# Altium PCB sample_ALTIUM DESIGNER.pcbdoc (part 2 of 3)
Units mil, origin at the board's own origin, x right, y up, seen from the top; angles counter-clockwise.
Board outline 2485.01 x 1905 mil, 6 copper layers (1 TallParts (2oz), 2 RTNS (2oz), 3 InternalPlane1 (2 oz), 4 InternalPlane2 (2 oz), 5 Signal (2oz), 6 LoParts (2oz)), stack 46.8 mil thick; 176 components, 89 nets, 769 pads, 0 vias.
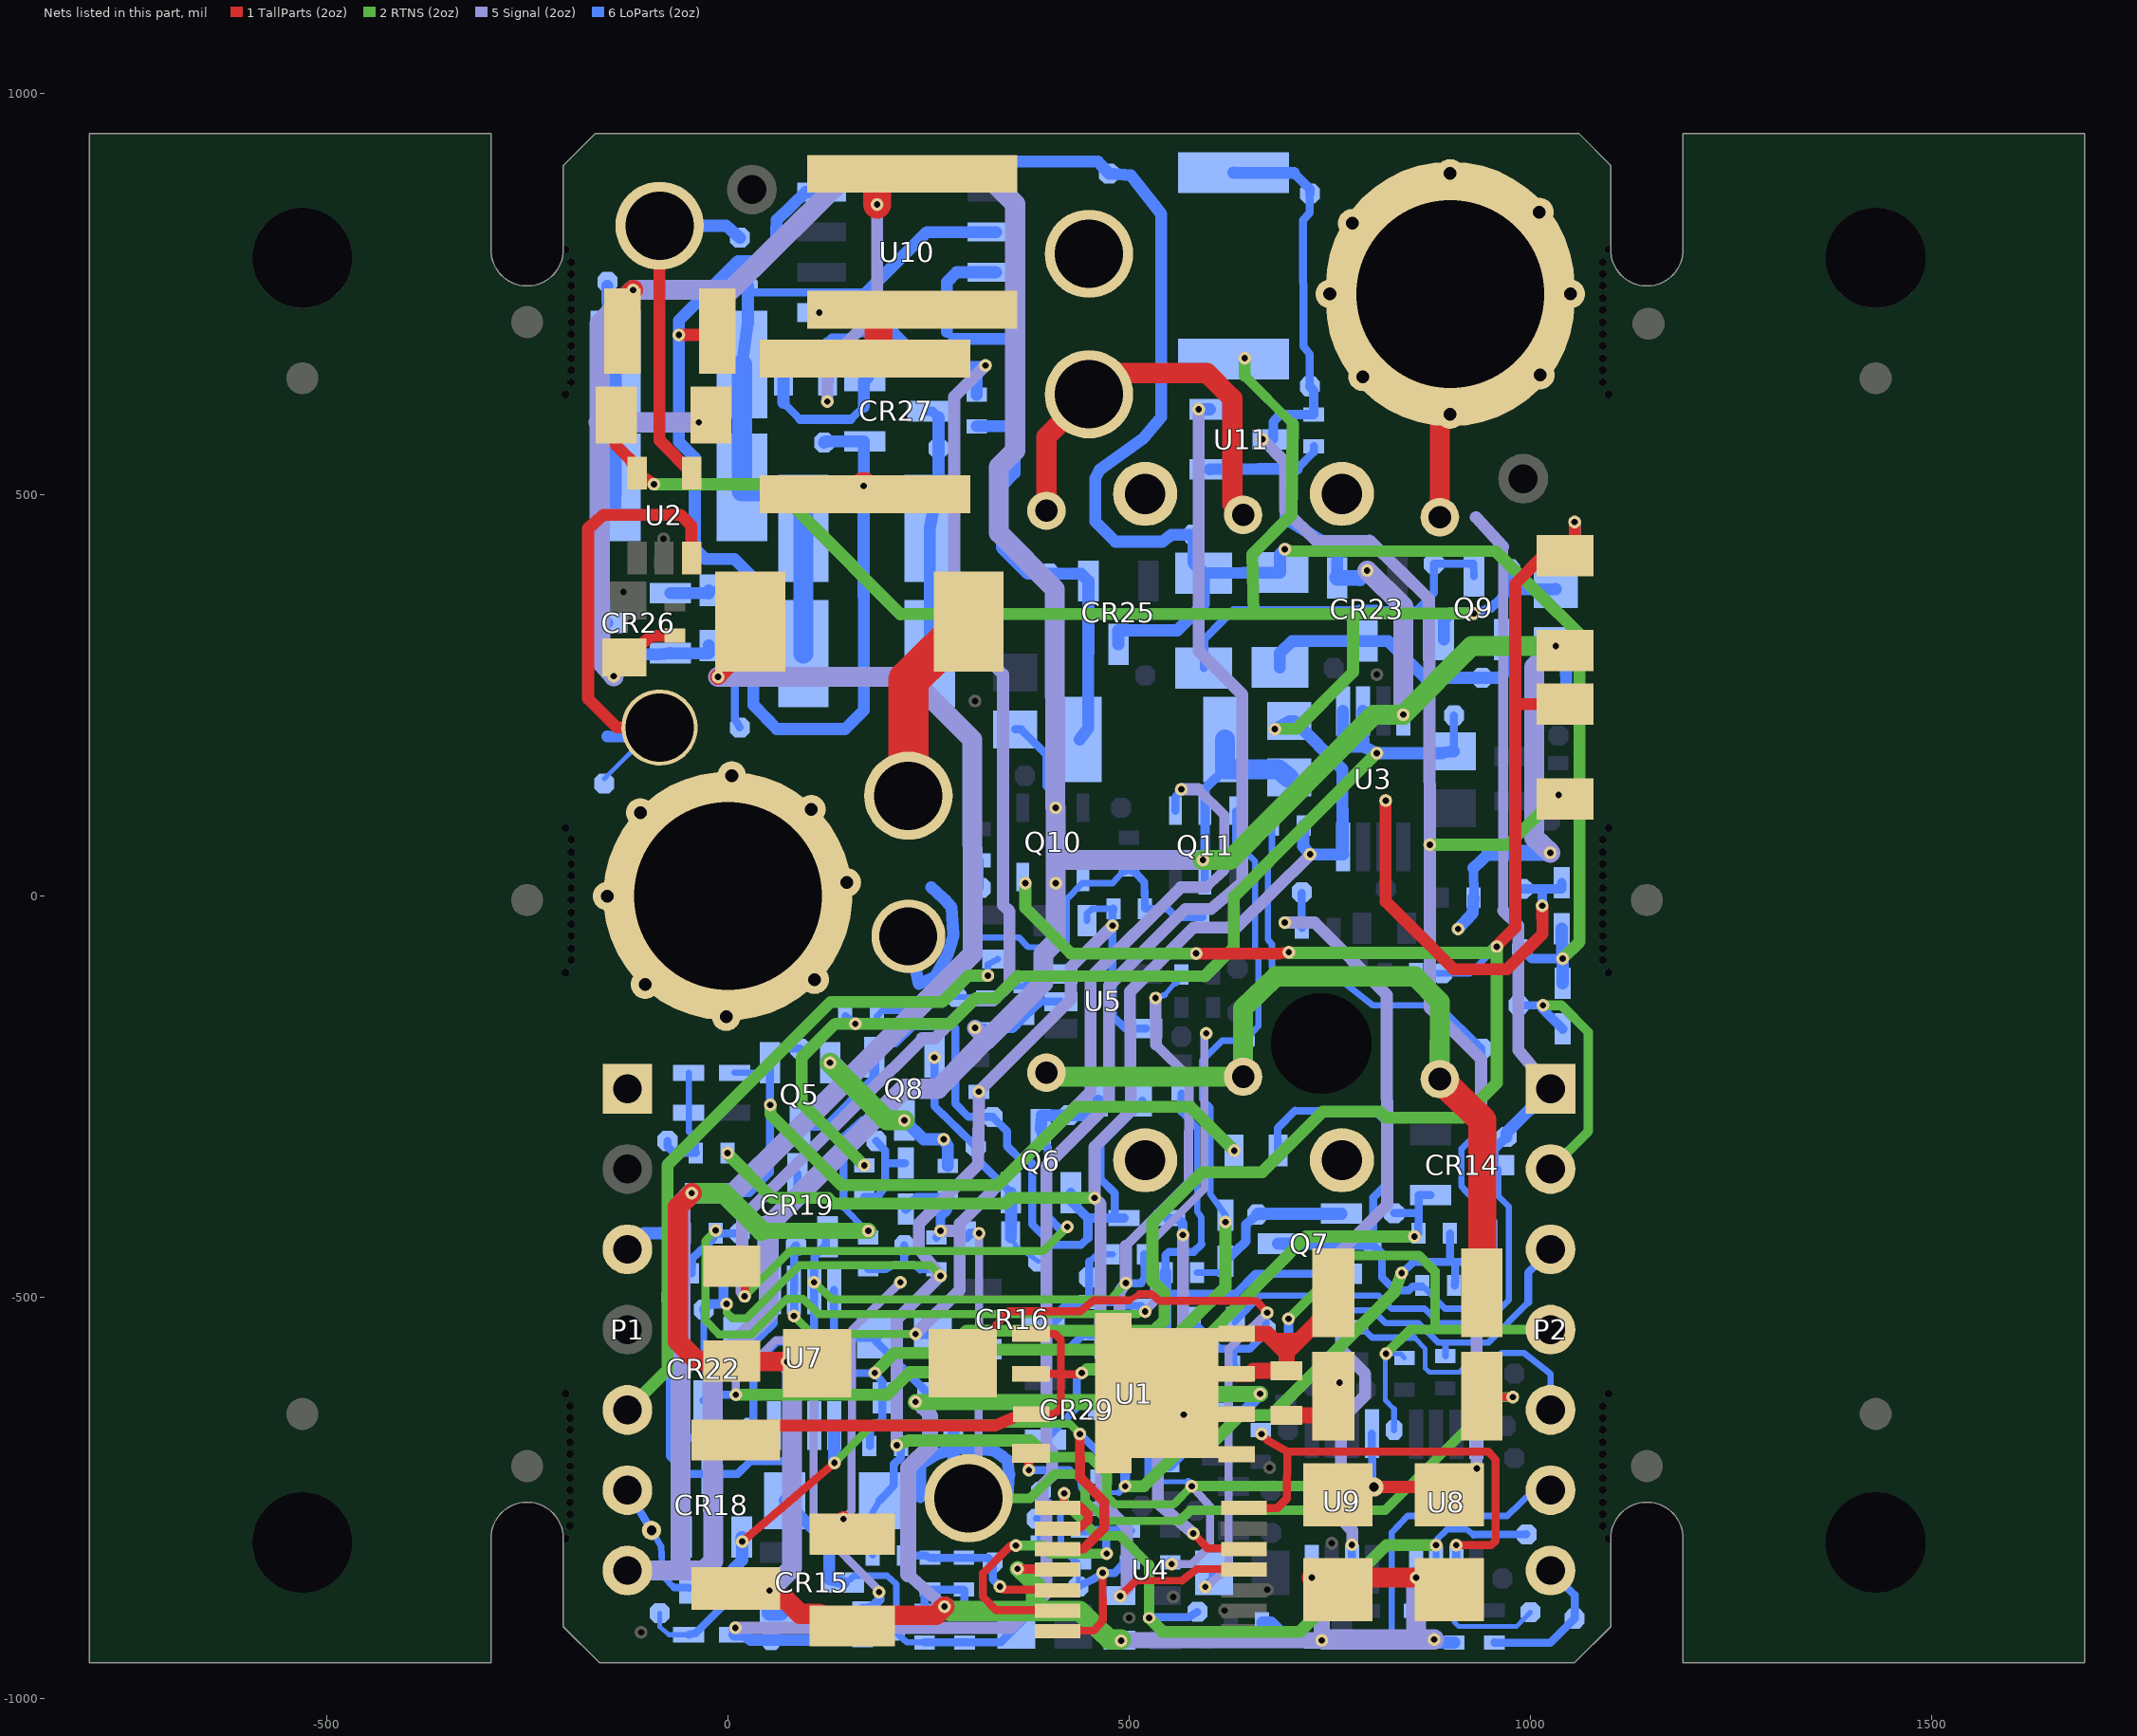
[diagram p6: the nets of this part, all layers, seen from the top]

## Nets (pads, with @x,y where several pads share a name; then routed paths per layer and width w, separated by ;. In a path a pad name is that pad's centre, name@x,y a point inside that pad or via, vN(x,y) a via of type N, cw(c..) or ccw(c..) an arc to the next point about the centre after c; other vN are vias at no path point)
5V_REG: C8.2 C13.1 C20.1 C21.1 C28.1 C33.2 pad.1@805,-736 pad.2@210.5,-684 pad.2@265.01,-473 pad.2@312.73,-243.69 pad.2@479.25,-36.85 pad.2@553,-832 pad.2@578,-735 pad.2@666,569 pad.2@874.6,64 pad.2@933,-713 pad.2@1035.01,126 pad.2@-1.5,-508 pad.8@220.01,-435 pad.8@725,635 pad.8@725,875 pad.8@-29.99,-515 R5.2 R9.2 R12.1 R14.2 R35.2 R36.2 R66.2 R67.2 R71.1 R86.2 R92.2 U5.5 U7.8 U8.8 U9.8 U11.3 | length 5291.2
  1 TallParts (2oz) w12: C20.1@760.01,-745.94 769.96,-736 pad.1@805,-736
  1 TallParts (2oz) w15: pad.1@805,-736 888,-736 C21.1@899,-745.94 917.5,-745.5 933,-730.5 pad.2@933,-713
  2 RTNS (2oz) w10: pad.2@-1.5,-508 -1.5,-519 6,-526 23.5,-526 89,-460 253,-460 pad.2@265.01,-473 ; 472.5,-747.5 482.5,-757.5 555.5,-757.5 pad.2@578,-735
  2 RTNS (2oz) w12: 451,-699 472.54,-719.54 472.5,-747.5
  2 RTNS (2oz) w13: 399,-699 451,-699 ; pad.2@578,-735 795,-735 pad.1@805,-736
  2 RTNS (2oz) w15: pad.2@210.5,-684 225,-678 377,-678 399,-699 ; pad.2@874.6,64 972.3,64 pad.2@1034.61,126.31
  5 Signal (2oz) w10: pad.2@554,-832 578,-832 601,-809 601,-760 pad.2@578,-735
  5 Signal (2oz) w15: pad.2@210.5,-684 210.5,-527.5 pad.2@265.01,-473 238,-439 238,-408 312,-334 pad.2@312.73,-243.69 ; pad.2@313,-243.42 313.5,-242.5 427.5,-128.5 427,-89.11 pad.2@479.25,-36.85 ; pad.2@666,569 694,541 694.5,480.5 733,442.5 799.5,443 873.5,370 874.75,64 874.69,63.92 pad.2@874.6,63.81 ; pad.2@874.6,64 pad.2@874.6,63.81 ; pad.2@933,-713 933,-266 938.5,-261 938.5,-203.11 874.6,-139.2 pad.2@874.6,63.81
  6 LoParts (2oz) w6: 528.5,-729.5 pad.2@573.5,-729.5
  6 LoParts (2oz) w8: pad.8@-29.99,-515 -30,-573 -55,-598 -55,-666 -45.5,-676 -5,-676 5.5,-687 45.5,-687 57.5,-676 U7.8@57.5,-659.65 ; R12.1@180.32,-821.27 180.32,-767.74 R9.2@189.06,-753 ; R5.2@447.57,-30.54 447.57,-21.93 453.77,-15.73 R86.2@480.31,-15.73 ; 524,-726 528.5,-729.5
  6 LoParts (2oz) w10: C13.1@175.01,-464.69 197,-464.5 206,-460 220,-460 ; R9.2@189.06,-753 207,-734 207,-707.5 215.5,-699.5 R67.2@215.41,-685 ; pad.8@220.01,-435 220,-460 ; pad.2@265.01,-473 R66.2@260,-464.69 240,-465 233,-460 220,-460 ; R86.2@480.31,-15.73 479,-22.5 pad.2@479.25,-36.85 479.5,-149.5 495.5,-165 U5.5@521,-165 ; 524,-726 524,-692 526.31,-689.69 C33.2@526.31,-678 ; pad.2@573.5,-729.5 pad.2@578,-735 ; pad.2@666,569 U11.3@679.37,569 ; pad.8@725,635 725,675 717,685 716.5,842 725,851 pad.8@725,875 ; U9.8@802.5,-669.35 803,-728 pad.1@805,-736 ; U8.8@932.51,-670.35 933,-676.5 pad.2@933,-713
  6 LoParts (2oz) w12: pad.8@-29.99,-515 -22.99,-508 pad.2@-1.5,-508 -5.3,-504.2 R14.2@-5.3,-470 ; pad.2@210.5,-684 214.69,-684 R67.2@215.69,-685 ; R36.2@551,-829.69 553,-831.69 pad.2@553,-832 ; U11.3@679.37,569 679.5,590.5 687.5,599.5 C28.1@730,599.69 730,629 pad.8@725,635 ; 705.5,900.5 725,881 pad.8@725,875
  6 LoParts (2oz) w15: R71.1@630,901.14 705.5,900.5
28V_BIAS_IN: CR7.1 P2.2 pad.2@1015.6,-136 pad.8@985,-136 | length 330.7
  2 RTNS (2oz) w10: pad.2@1015.81,-136.2 pad.2@1016,-136
  2 RTNS (2oz) w12: pad.2@1015.6,-136 1016,-136 1038.5,-136 1072,-169.5 1072,-293 P2.2@1025,-340
  6 LoParts (2oz) w10: pad.8@985,-136 pad.2@1015.6,-136
  6 LoParts (2oz) w12: pad.2@1015.6,-136 1015.6,-141.1 CR7.1@1040,-165.5
28VA: CR8.1 CR13.1 E1.1 E2.1 FL1.2 FL2.2 pad.2@819.6,119 pad.2@1014.61,-12 pad.8@989.61,9 | length 1071.2
  1 TallParts (2oz) w15: 819.5,-7 pad.2@819.6,118.49 ; pad.2@1014.61,-12 1015,-47 971,-91 904,-91 819.6,-6.6 pad.2@819.6,118.49 ; pad.2@819.6,118.49 pad.2@819.6,119 pad.2@819.6,118.49
  1 TallParts (2oz) w50: E1.1@225.01,125 225,269 299.5,342.51 CR13.1@300,343
  6 LoParts (2oz) w12: pad.8@989.61,9 1014.5,9 ; pad.2@1014.61,-12 1014.5,9 ; CR8.1@1039,16.5 1039,9 1014.5,9
  6 LoParts (2oz) w15: E2.1@225.01,-50 238,-109.5 248.42,-105.07 258,-101 267,-85 271.57,-77.16 274,-73 276.19,-65.99 279,-57 281,-48.5 ; E2.1@253.5,11 268.32,-2.51 270.51,-4.51 273.88,-8.47 279,-14.5 280.89,-46.71
28VBUS: C4.1 FL1.1 FL2.1 P1.1 pad.2@144,-776 pad.2@215,-481 pad.5@5,150 pad.5@104,108 pad.5@108,-104 pad.5@148,17 pad.5@-2,-150 pad.5@-103,-110 pad.5@-109,104 pad.5@-150,0 TRM1.1 | length 344.5
  1 TallParts (2oz) w20: pad.2@144,-776 C4.1@155.01,-792.91
  5 Signal (2oz) w10: pad.2@144,-776 154,-766 155.01,-539.99 pad.2@215,-481
28VOUTPUT: CR14.3 E5.1 E6.1 P2.1 pad.5@750,750 pad.5@778,838 pad.5@791,647 pad.5@900,600 pad.5@900,900 pad.5@1011,852 pad.5@1012,649 pad.5@1050,750 pad.8@970,-300 R17.1 R18.1 R19.1 R58.2 TRM2.1 | length 2063.8
  1 TallParts (2oz) w25: R17.1@397,480 397,571.99 E5.1@450.01,625 476.51,651.5 597,651.5 628.5,620 R18.1@628.5,488.51 ; R19.1@887,472 887,587 pad.5@900,600
  5 Signal (2oz) w12: 966,-18 966,434.99
  5 Signal (2oz) w15: 932.01,472 966,434.99 ; 966,-18 985,-37 985,-192 P2.1@1025,-240
  6 LoParts (2oz) w8: R58.2@631.56,-531 632.05,-530.5 664.56,-497.5 810.5,-497.5 827,-514 868,-514 886,-532 944,-532 973,-503 973,-386.79 960.01,-373.79 960.01,-340 CR14.3@954.37,-335
  6 LoParts (2oz) w12: CR14.3@954.37,-335 954.5,-315.5 pad.8@970,-300
  6 LoParts (2oz) w15: pad.8@970,-300 970,-295 P2.1@1025,-240
28VR: C23.1 CR7.2 CR8.2 CR25.3 pad.2@694,432 pad.2@1040.01,-78 pad.2@-61,699 pad.8@475,900 pad.8@580.01,450 pad.8@989.61,-66 R69.2 R70.2 R73.1 U10.8 | length 3063
  1 TallParts (2oz) w15: pad.2@-61,699 C23.1@-13,699
  2 RTNS (2oz) w15: pad.2@694,432 700,430 956.5,429.5 1061,326.61 1061,-57.01 pad.2@1040.01,-78
  6 LoParts (2oz) w12: pad.8@989.61,-66 1001.61,-78 pad.2@1039.61,-78
  6 LoParts (2oz) w15: R73.1@31.56,381 31.56,396.44 8,420 -28,420 -41,433 -41,546.16 -61,566.16 pad.2@-61,699 -61,717 13,791 38,791 59,812 60,812 61,842 97,877 U10.8@114,877 ; U10.8@113,878 113,900 129,915 461,915 pad.8@475,900 502,898 540,849.5 540,596.5 517.5,570 463,531 458,520.5 458,466.5 483,441.5 541.5,441.5 552.5,450 pad.8@580.01,450 R69.2@580.01,417.48 ; CR25.3@486.5,331 CR25.3@486.61,313.63 ; CR25.3@486.61,331 560,331 593,364 R69.2@593,402.06 ; pad.2@694,432 688,426 R70.2@688,403.06 R69.2@593,402.06 ; CR8.2@1039,-40.5 pad.2@1039.61,-78 ; CR7.2@1040,-108.5 pad.2@1040.01,-78 ; R69.2@580.01,417.48 R69.2@593,402.06 ; R69.2@580.01,417.48 580.01,415.04 R69.2@593,402.06
+20V: C5.1 C6.1 C22.1 C29.1 pad.2@457,-376 pad.2@489.01,-872 pad.2@644,670 pad.2@681.62,208 pad.2@725.43,52 pad.2@929.6,352 pad.2@-0.3,-320 pad.2@-92,513 pad.8@974.61,407 Q9.2 R6.2 R20.2 R71.2 U2.5 U3.8 U4.4 | length 4032.4
  1 TallParts (2oz) w9: 509,-852.5 566,-852.5
  1 TallParts (2oz) w10: pad.2@489.01,-872 509,-852.5 ; 566,-852.5 584,-838.5 U4.4@643.14,-838.22
  1 TallParts (2oz) w15: C6.1@-139.06,599 -139.06,561.56 -122,544.5 U2.5@-113,527 pad.2@-93,514 ; C6.1@-138.06,591 C6.1@-122,572
  2 RTNS (2oz) w12: 644,648 704,588
  2 RTNS (2oz) w15: pad.2@-92,513 54,513 156,411 156,410 215,351 779,351.79 ; pad.2@-0.3,-320 -0.99,-320 -0.64,-320.34 55,-376 124.97,-376 131.97,-383 346.03,-383 353.03,-376 pad.2@457,-376 ; 644,648 pad.2@644,670 ; 655,352 653.5,426 702.5,475 704,588 ; pad.2@681.62,208 708.47,208.39 779,278.92 779,351.79 ; pad.2@929.6,352 779,351.79
  5 Signal (2oz) w15: pad.2@489.01,-872 497.23,-863.78 497.23,-786.23 465,-754 465,-711 475,-701 475,-584 464,-573 464.5,-383.5 pad.2@457,-376 457,-312.5 502,-267.5 501,-119 580.5,-39 634,-39 725,51 pad.2@725.43,52
  6 LoParts (2oz) w12: pad.2@929.6,352 951,359 975,382
  6 LoParts (2oz) w15: pad.2@681.62,208 699.88,217.91 700.04,218 706.04,218 765.61,158 765.98,61.35 U3.8@766.01,52 ; R20.2@717.29,87.73 717,62 725.17,52 pad.2@725.43,52 U3.8@766.01,52 ; U3.8@766.61,52 766.5,52 U3.8@766.01,52 ; Q9.2@892.2,319.63 892.2,344.6 899.6,352 pad.2@929.6,352 ; pad.8@974.61,407 975,382 C22.1@1031.61,382.43
+45V: C3.1 C27.1 pad.2@21,-498.5 pad.2@124,616 pad.2@186,861.5 pad.2@321,661 pad.2@423,-412 pad.8@275,660 pad.8@425,-273 Q6.3 R16.2 R75.2 R76.2 | length 2710.1
  1 TallParts (2oz) w10: C3.1@5.01,-460.94 20.5,-475.5 pad.2@21,-498.5
  1 TallParts (2oz) w35: pad.2@186,861.5 186,899.65 186,902 C27.1@187.5,903.5
  2 RTNS (2oz) w10: pad.2@21,-498.5 77.5,-442 393.01,-442 pad.2@423,-412
  5 Signal (2oz) w15: pad.2@21,-498.5 17.5,-493 18,-401 243.65,-177 ; pad.2@124,616 124,665 186,727 pad.2@186,861.5 ; 242,-177 243.65,-177 ; pad.2@321,661 282,622 282,336 343,276 343,-11 351,-19 351,-110 331,-130 305,-130 258,-177 243.65,-177
  6 LoParts (2oz) w10: Q6.3@390,-290.63 390,-304 399,-313 399,-399 413,-414 pad.2@423,-412
  6 LoParts (2oz) w12: 125,689 130,695 154,695 161,702 206,702
  6 LoParts (2oz) w15: R75.2@124.56,643 125,689 ; 206,702 248,659 275,659 310,659 ; R76.2@310,624.69 310,659 ; pad.2@321,661 319,659 310,659 ; Q6.3@390,-290.63 391,-273 pad.8@425,-273 453,-273 461.5,-264.5 R16.2@461.44,-255
CONTROL: CR5.1 CR22.3 pad.2@10,-621 pad.2@188.47,-867 pad.2@620,-406 pad.8@644,-180 Q11.3 R8.1 | length 1875.9
  2 RTNS (2oz) w15: pad.2@10,-621 198,-621.5 227,-593 290,-593 318,-565 541,-565 620,-487 pad.2@620,-406
  5 Signal (2oz) w10: pad.2@10,-621 10,-603 60,-553 90,-553 107,-570 107,-783 pad.2@188.49,-864.99
  6 LoParts (2oz) w8: pad.2@620,-406 CR5.1@620,-397.5 601,-371 601,-263 591,-253 591,-205 616,-180 pad.8@644,-180 661,-162 661,-77 657,-70 657,43 632.5,67.5 Q11.3@632.5,106.31
  6 LoParts (2oz) w10: CR22.3@-30,-628.37 -22.5,-621 pad.2@10,-621
  6 LoParts (2oz) w12: R8.1@168,-887.31 172.69,-887.31 179.5,-885.5 189,-876.5 188.44,-867 188.47,-866 pad.2@188.5,-865
FASTTRIPCURRENT: pad.2@159,-159 pad.2@170.01,-335.31 pad.2@808.62,178 pad.8@904.61,225 R28.1 R64.1 R90.2 U3.1 U3.2 | length 1361.4
  2 RTNS (2oz) w15: pad.2@170.01,-335.31 92,-257.3 92,-201 134,-159 pad.2@159,-159 277,-159 309,-127 334,-127 361.5,-99.5 594,-100 630.5,-63.5 630.5,-1 808.22,178 pad.2@808.62,178
  6 LoParts (2oz) w10: R90.2@146.62,-149.46 pad.2@159,-159 ; R28.1@904.33,180.43 pad.8@904.61,225
  6 LoParts (2oz) w15: U3.1@766.11,230.65 766.11,197.5 775,186 792,186 ; U3.2@791.11,230.64 792,186 ; R28.1@904.33,180.43 890,178 pad.2@808.62,178 792,186
FASTTRIPSET: P1.3 R60.1 | length 78.6
  6 LoParts (2oz) w15: P1.3@-124.99,-440 -104.99,-420 R60.1@-54.68,-420
GND: C3.2 C4.2 C5.2 C6.2 C7.2 C9.2 C10.2 C11.2 C13.2 C15.2 C16.2 C18.2 C19.2 C20.2 C21.2 C22.2 C23.2 C28.2 C29.2 C30.2 C33.1 CR12.2 CR13.2 CR15.1 CR16.1 CR20.1 CR23.1 P1.7 pad.2@52.01,-865 pad.2@74.01,-580 pad.2@127.41,-207.63 pad.2@175.01,-417 pad.2@220.01,-279.37 pad.2@234,-630 pad.2@269,-303 pad.2@270,-885 pad.2@308,-164 pad.2@361,-838 pad.2@408.6,16 pad.2@408.6,110 pad.2@490.01,-927.56 pad.2@592,45 pad.2@663,-620 pad.2@727.51,-849 pad.2@740,-927 pad.2@796.5,405.5 pad.2@841.51,226 pad.2@857.51,-849 pad.2@880,-926 pad.2@909.7,-41 pad.2@1024.62,54 pad.2@1031.61,311.57 pad.2@-12,273 pad.2@-36,590 pad.2@-44.99,-370 pad.2@-118,755 pad.2@-142,274 Q5.2 Q7.2 Q8.3 Q10.2 Q10.5 Q11.2 Q11.5 R7.1 R10.1 R23.1 R25.1 R27.1 R27A.1 R32.1 R34.1 R39.1 R40.1 R52.1 R61.1 R62.1 R65.1 R68.1 R72.1 R80.1 R91.1 R93.1 U3.4 U4.11 U5.2 U7.4 U8.4 U9.4 U11.1 | length 12700.7
  1 TallParts (2oz) w12: pad.2@361,-838 U4.11@410.86,-838.5
  1 TallParts (2oz) w15: pad.2@-142,274 R27.1@-129,297.57 -95,324 R80.1@-66,324.31 ; C6.2@-35,591 C6.2@-20.94,599 ; pad.2@1031.61,311.57 C7.2@1043,305.94
  1 TallParts (2oz) w20: pad.2@-12,273 27,315.5 CR13.2@28,342 CR13.2@28,343
  1 TallParts (2oz) w25: C23.2@-131.06,704 -131.06,741.94 pad.2@-118,755 ; pad.2@-44.67,-370 -44.83,-370.16 -62,-387 -62,-555 -38,-579 C3.2@5.01,-579.06 pad.2@74.01,-580 CR20.1@111.5,-580 ; CR12.2@10.01,-865 pad.2@52.01,-865 52,-876 72,-876 90,-894 114,-894 155.01,-907.09 195,-896 259.5,-895.5 pad.2@270,-885 ; pad.2@727.51,-849 C20.2@760.01,-849 ; C20.2@760.01,-864.06 C20.2@760.01,-849 ; C21.2@899,-864.06 883.94,-849 pad.2@857.51,-849 C20.2@760.01,-849
  2 RTNS (2oz) w20: 42,-417 pad.2@175.01,-417 ; pad.2@234,-630 541.5,-630 550.5,-620 pad.2@663,-620 ; pad.2@361,-838 384,-860
  2 RTNS (2oz) w25: pad.2@-44.99,-370 -5,-370 42,-417 ; pad.2@127.41,-207.63 198,-279 pad.2@220.01,-279.37 ; pad.2@270,-885 277,-890.5 384,-890.5 ; 384,-860 384,-890.5 ; pad.2@490.01,-926 475.5,-926 438.5,-890.5 384,-890.5 ; pad.2@592,45 625.6,45 804.6,226 pad.2@841.51,226 841.62,226 926.68,311.57 pad.2@1031.61,311.57
  5 Signal (2oz) w15: 225,-845 pad.2@270,-885 ; pad.2@234,-630 252,-648
  5 Signal (2oz) w20: 225,-845 225,-712 252,-685 252,-648 ; pad.2@308,-164 321.81,-178.52 ; pad.2@490.89,-926.69 pad.2@740,-927 740,-861 pad.2@727.51,-849
  5 Signal (2oz) w25: -161,590 -159.71,590 ; pad.2@-142,274 -159,294 -159.71,590 ; P1.7@-124.99,-840 -60,-840 ; pad.2@-36,590 -159.71,590 ; pad.2@-12,273 226.6,273 304.6,195 305,-72 ; pad.2@52.01,-865 80,-837 80,-591 pad.2@74.01,-580 ; pad.2@127.41,-207.26 127.6,-207.44 149,-228.5 ; 304,-73 149,-228.5 ; pad.2@408,110 407.5,382.5 337.5,452.5 337.5,534.5 358,555 358,862 314,906 157,906 3.84,754.84 pad.2@-118,755 -160,713 -159.71,590 ; pad.2@408.6,110 408.5,45 ; 409,44 408.5,45 ; pad.2@592,45 408.5,45 ; pad.2@741.69,-926 857.5,-926 ; pad.2@796.5,405.5 841.5,361 pad.2@841.51,226 ; pad.2@857.51,-849 857.5,-926 ; pad.2@880,-926 857.5,-926 ; pad.2@1024.62,54 1004.6,73.01 1004.6,285.55 pad.2@1031.61,311.57 ; -60,-840 -30,-840 -18,-828 -19,-587 51,-518 51,-410 220,-240 262,-240 321.81,-178.52 322.08,-178.25 322.2,-179.13 393,-108 393,-72 408.6,-56.4 pad.2@408.6,16 408.5,45 ; -60,-840 -59,-839 -59,-384.01 pad.2@-44.99,-370 7,-370 149,-228.5
  6 LoParts (2oz) w8: 144,-387 C13.2@172.01,-417 ; 565.27,-269.27 585,-289 585,-393 590,-400.5 590,-434
  6 LoParts (2oz) w10: 132.51,-547.51 U7.4@132.5,-490.35 ; 144,-387 144,-300 168,-279 217,-279 Q8.3@220.01,-279.37 ; C13.2@172.01,-417 pad.2@175.01,-417 ; R65.1@184.57,-548.27 184.57,-554.57 247.57,-617.57 R68.1@247.57,-625 244.98,-627.6 242.57,-630 pad.2@234,-630 ; C9.2@245.01,-890.31 245.01,-870.67 R10.1@252,-863.69 C10.2@294,-863.69 295.01,-864.7 R61.1@295.01,-890.31 ; pad.2@308,-164 319.5,-164 R91.1@322.27,-165.68 355,-165.68 C30.2@369,-151.69 390,-131.5 U5.2@415,-131.5 ; CR16.1@315.63,-564.4 424.6,-564.4 444.32,-544.69 R62.1@450.01,-544.69 ; R27A.1@358,207.57 365.43,207.57 397,176 397,137 408.6,125.4 408.6,110.31 pad.2@408.6,110 ; 545,-495.5 545.21,-495.5 633,-495 657.5,-470.5 ; R25.1@545.32,-469 545.32,-447.19 549.5,-443 580.5,-443 590,-434 ; 565.27,-269.27 R93.1@565.27,-245.68 ; pad.2@592,45 594.5,40.5 Q11.5@594.5,19.69 ; 657.63,-470.6 Q7.2@764.37,-470.4 ; 709,532 730,553 C28.2@730,560.31 ; pad.2@727.51,-849 U9.4@727.5,-838.65 ; pad.2@857.51,-849 U8.4@857.51,-839.65
  6 LoParts (2oz) w12: pad.2@594.5,47.5 Q11.2@594.5,106.31 594.5,134 R72.1@619.5,158 ; 929,35 R52.1@929.77,-1.08
  6 LoParts (2oz) w15: pad.2@74.01,-580 101,-580 133,-548 R65.1@184.57,-548.27 ; Q8.3@220.01,-279.37 244,-303 pad.2@269,-303 274,-311 C16.2@274,-336.31 ; R68.1@244.98,-627.6 247.57,-627.6 297.4,-627.6 315.63,-609.37 CR16.1@315.63,-564.4 ; C9.2@245.01,-890.31 270,-890.31 R61.1@295.01,-890.31 ; R62.1@450.01,-544.69 474,-545 479,-550 C11.2@515.01,-549.69 541,-550 ; R25.1@545.32,-469 545.21,-495.5 545,-546 541,-550 ; R40.1@550.01,-709 566.69,-692.33 C33.1@566.69,-678 570,-678 605.56,-642.44 R34.1@610.01,-642.44 643.5,-642.5 pad.2@663,-620 ; 575,-584 541,-550 ; 576,-585 R23.1@590.33,-585 ; U11.1@600.63,531.6 661,532 695,532 ; R32.1@665.69,-905 677.01,-905 700,-928 C15.2@731.01,-928.69 pad.2@740,-927 ; 709,532 695,532 ; CR23.1@759.21,396.37 759,431 695,470 695,532 ; C19.2@855.01,-929.69 880,-929.69 C18.2@905.01,-929.69 ; pad.2@909.7,-41 928,-21 R52.1@928.98,-2 ; 929,35 949,54 ; C22.2@1031.61,311.57 1044.3,298.88 R39.1@1044.6,247
  6 LoParts (2oz) w20: pad.2@52.01,-865 52,-892.4 52,-892.5 CR15.1@65.63,-892.4 ; CR23.1@759.21,396.37 787,396 pad.2@796.5,405.5 ; 949,54 pad.2@1024.62,54
  6 LoParts (2oz) w25: R72.1@619.55,195 619.5,158 619.55,158 686,158 C5.2@699.18,147.13
NetC7_1: C7.1 C8.1 pad.2@183,-594 pad.2@370.6,16 pad.2@583.5,-71.5 pad.2@699,-70 pad.2@958.01,-63 pad.2@1055,466 pad.8@890,-96 pad.8@1055,435 Q10.3 R57.2 R67.1 R68.2 U7.6 | length 2857.9
  1 TallParts (2oz) w15: pad.2@583.5,-71.5 686.5,-71.5 pad.2@699,-70 ; pad.2@958.01,-63 958.01,-62.04 981,-39.06 981,239 ; C8.1@1043,235 C8.1@1043,239.06 1043,238.94 981,239 ; pad.2@1055,466 1055,434 C7.1@1043,424.06 1016,424 981,389 981,239
  2 RTNS (2oz) w15: pad.2@183,-594 208,-569 269.47,-569 297,-541.5 530,-541.5 544,-529 544,-494.5 529,-478.75 ; pad.2@370.6,16 370.6,-14.6 427.5,-71.5 pad.2@583.5,-71.5 ; 529,-479.5 529,-478.75 ; pad.2@699,-70 699,-70.69 946.93,-70.69 ; 949.93,-69.69 pad.2@957.61,-63 ; pad.2@958.01,-63 958.01,-232.99 915,-276 820,-276 812.5,-268.5 741,-268.5 665.5,-344 591,-344 529,-406 529,-478.75
  6 LoParts (2oz) w8: R57.2@857.69,-96 pad.8@890,-96 925.01,-96 pad.2@958.01,-63
  6 LoParts (2oz) w10: U7.6@107.5,-659.65 107.5,-621 137,-594.5 pad.2@183,-594 192.5,-605 R68.2@192.45,-625 192.5,-651.5 177,-666 R67.1@177.01,-685
  6 LoParts (2oz) w15: pad.8@1055,435 pad.2@1055,466
NetC9_1: C9.1 CR15.3 pad.8@208,-915 R9.1 R11.2 R59.2 R61.2 | length 503.3
  6 LoParts (2oz) w8: CR15.3@153,-851 158,-846.5 198.5,-846.5 210,-857 210.5,-910 pad.8@208,-915 ; pad.8@208,-916 223.5,-929.5 C9.1@245.01,-929.69
  6 LoParts (2oz) w10: C9.1@245.01,-929.69 R61.2@295.01,-929.69 340,-929.5 R59.2@359.58,-910 390.01,-879.57 R11.2@390.01,-844.69
  6 LoParts (2oz) w15: R9.1@70.94,-753 126.5,-808.5 126.5,-851 CR15.3@144.37,-855
NetC10_1: C10.1 pad.2@339.01,-860 pad.8@330,-830 R10.2 R12.2 U4.12 | length 220.5
  1 TallParts (2oz) w10: pad.2@339.01,-860 342.83,-863.82 U4.12@410.86,-863.82
  6 LoParts (2oz) w10: R12.2@219.69,-821.27 246.5,-821.5 R10.2@252,-824.31 C10.1@294,-824.31 324.32,-824.31 pad.8@330,-830 330,-850.99 pad.2@339.01,-860
NetC11_1: C11.1 CR16.3 pad.2@520,-517.5 pad.2@596,-171 pad.2@-15,-416.5 pad.8@15.01,-420 pad.8@450.01,-475 R14.1 R60.2 R62.2 R96.1 | length 1402
  2 RTNS (2oz) w10: pad.2@-15,-416.5 -28,-429.5 -28,-528 -11,-546 29.5,-546 73,-502 94,-502 113.01,-520.5 511,-520.5 pad.2@520,-517.5
  5 Signal (2oz) w10: pad.2@520,-517.5 531,-506 531,-427.5 594,-364.5 594,-175 pad.2@596,-171
  6 LoParts (2oz) w8: 450.01,-455.27 460,-446.5 R96.1@479.32,-446.27
  6 LoParts (2oz) w10: R14.1@-44.67,-470 -44.5,-451.5 -19,-428 R60.2@-15.31,-420 -15,-420 pad.8@15.01,-420 ; 450.01,-455.27 pad.8@450.01,-475 R62.2@450.01,-505.31 458,-506 482,-506 491.33,-510.31 C11.1@515.01,-510.31 ; C11.1@516.47,-518.15 516.43,-517.92 C11.1@515.01,-510.31 ; pad.2@520,-517.5 C11.1@515.01,-510.31
  6 LoParts (2oz) w12: R60.2@-15,-419.69 pad.2@-15,-416.5
  6 LoParts (2oz) w15: CR16.3@394.37,-527 407,-527 428.69,-505.31 R62.2@450.01,-505.31
NetC14_1: C14.1 pad.2@359,-809 pad.2@472,-819 pad.8@385,-775.5 R11.1 R13.1 U4.13 | length 459.6
  1 TallParts (2oz) w10: pad.2@359,-809 352.5,-809 318,-843.5 318.01,-873 334.42,-889.41 U4.13@410.86,-889.41
  2 RTNS (2oz) w12: pad.2@359,-809 391,-809 401,-819 pad.2@472,-819
  6 LoParts (2oz) w10: pad.2@359,-809 384,-809 R11.1@390.01,-805.31 390.28,-780 pad.8@385,-775.5 ; 467,-790.31 471,-790.31 pad.2@472,-819
  6 LoParts (2oz) w12: R13.1@440,-790.31 471,-790.31 C14.1@501,-790.31
NetC14_2: C14.2 pad.2@467,-843 pad.8@390,-742 pad.8@437,-860 R13.2 R63.2 U4.14 | length 378.6
  1 TallParts (2oz) w10: U4.14@415.01,-915 456.01,-915 467.5,-902.5 pad.2@467,-843
  6 LoParts (2oz) w6: pad.8@437,-860 R13.2@437.01,-832.69
  6 LoParts (2oz) w8: pad.8@390,-742 395.5,-751 414.5,-766 ; R13.2@435,-829.69 415,-814 414.5,-766 ; R63.2@464.73,-762.69 464.59,-762.78 458,-767 414.5,-766
  6 LoParts (2oz) w10: pad.8@437,-860 455,-851 pad.2@467,-843 482,-843 C14.2@495.01,-829.69
  6 LoParts (2oz) w12: C14.2@495.01,-829.69 C14.2@501,-829.69
NetC15_1: C15.1 pad.2@694,-33 pad.2@777.5,-808 pad.8@715,5 R15.2 U9.2 | length 1116
  5 Signal (2oz) w15: pad.2@694,-33 731,-33 821,-123 821.5,-384.5 764,-442 764,-565 794,-595 794,-622 764,-652 764,-776 778,-790 pad.2@778,-808
  6 LoParts (2oz) w8: C15.1@731.01,-889.31 745.01,-885 765.01,-885 777,-873 U9.2@777.5,-838.65
  6 LoParts (2oz) w10: pad.2@694,-33 R15.2@715,-33 ; pad.8@714.61,3.99 715,0 R15.2@715,-33 ; R15.2@715.32,-40 R15.2@715,-33 ; U9.2@777.5,-838.65 pad.2@777.5,-808 U9.2@777.5,-838.65
NetC16_1: C16.1 CR10.2 pad.2@82.5,-523 pad.2@234,-545.5 pad.2@265.01,-417 pad.2@565,133 pad.8@85,-435 Q11.1 R65.2 R66.1 U7.2 | length 1329.2
  2 RTNS (2oz) w10: pad.2@82.5,-523 105,-545.5 pad.2@234,-545.5
  5 Signal (2oz) w12: 586,133 618.5,101 618.5,32 596,11
  5 Signal (2oz) w15: pad.2@234,-545.5 289,-490.5 289,-417 ; pad.2@265.01,-417 289,-417 ; pad.2@565,133 586,133 ; 596,11 564.5,11 452,-101.5 452,-244 289,-408 289,-417
  6 LoParts (2oz) w10: pad.2@82.5,-523 82.41,-490.36 U7.2@82.5,-490.35 pad.8@82.51,-437.5 ; pad.8@82.51,-437.49 pad.8@85,-435 ; R66.1@260,-425.31 pad.2@265.01,-417 ; Q11.1@557.5,106.31 557.5,123 pad.2@565,133
  6 LoParts (2oz) w12: CR10.2@222,-389.5 235.82,-375.69 C16.1@274,-375.69 274,-390.5 265.01,-399.49 pad.2@265.01,-417 ; pad.2@234,-545.5 252.67,-545.5 R65.2@255.44,-548.27
NetC18_1: C18.1 pad.2@665,-670 pad.2@907.5,-808.5 pad.8@1000,-892 R56.2 U4.7 U8.2 | length 773.5
  1 TallParts (2oz) w10: U4.7@643.14,-762.23 684.77,-762.23 696.5,-750.5 697,-692 ; pad.2@665,-670 674,-679 697,-692 ; pad.2@907.5,-808.5 951,-808.5 956.5,-803 956.5,-702 947.5,-692 697,-692
  6 LoParts (2oz) w6: C18.1@905.01,-890.31 905.01,-904.5 910.5,-909.5 983,-909.5 pad.8@1000,-892
  6 LoParts (2oz) w8: C18.1@905.01,-890.31 907.51,-887.81 U8.2@907.51,-839.65
  6 LoParts (2oz) w10: U8.2@907.51,-839.65 pad.2@907.5,-808.5
NetC19_1: C19.1 pad.2@419,-744 pad.2@525,-899 pad.2@882.5,-808.5 pad.8@585,-891.5 pad.8@995,-795 U4.8 U4.9 U8.3 | length 991.1
  1 TallParts (2oz) w10: U4.8@418.5,-761 pad.2@419,-744
  1 TallParts (2oz) w12: U4.8@410.87,-761.23 439.5,-761.5 448.5,-770 448.5,-777.5 U4.9@438,-787
  2 RTNS (2oz) w12: pad.2@419,-744 419,-755 461,-797 489,-797 525,-833
  2 RTNS (2oz) w13: pad.2@525,-898 525,-833
  2 RTNS (2oz) w15: pad.2@525,-899 541,-915 541,-916.5 712.5,-916.5 820.5,-808.5 pad.2@882.5,-808.5
  6 LoParts (2oz) w8: C19.1@855.01,-890.31 862.7,-890.31 882.5,-872 U8.3@882.51,-839.65 pad.2@882.5,-808.5 882.01,-803 896.5,-788.5 919.5,-788.5 929,-795.5
  6 LoParts (2oz) w10: pad.2@525,-898 574,-898 pad.8@585,-891.5 ; 929,-795.5 pad.8@995,-795
NetC24_1: C24.1 C31.1 CR26.3 pad.8@-150,765 | length 437.2
  6 LoParts (2oz) w15: CR26.3@-160,346 CR26.3@-150.37,340 ; CR26.3@-160,346.04 -159.5,469 -140,485.5 C31.1@-139.74,509 C24.1@-139.74,662 -149,676 pad.8@-149.99,760
NetC24_2: C24.2 C26.2 C31.2 C32.2 pad.8@25,760 U10.2 | length 881.4
  6 LoParts (2oz) w10: pad.8@25,760 27,752 173,752
  6 LoParts (2oz) w15: C24.2@17.74,662 25,713 pad.8@25,760 ; 173,752 248,827 329.43,827 U10.2@334,827
  6 LoParts (2oz) w25: C24.2@17.74,662 C31.2@17.74,509 17.43,508.98 17.74,504 94,504 C26.2@94.26,458 C32.2@94.26,302
NetC25_1: C25.1 CR27.1 pad.2@169.26,511 pad.8@120,565 R74.2 | length 627.9
  1 TallParts (2oz) w35: C25.1@169.26,502.09 pad.2@169.26,511
  6 LoParts (2oz) w15: R74.2@31.56,312 32,238 60.99,208 146,208 169.63,231.63 pad.2@169.26,511 ; pad.8@120,565 121.6,566.6 169.63,566.6 pad.2@169.63,511.37
NetC25_2: C25.2 C27.2 CR25.1 pad.2@114,727 pad.8@400.44,401.57 R72.2 R76.1 U10.3 U10.5 | length 1064.9
  1 TallParts (2oz) w35: C25.2@171,669.65 188,686.65 C27.2@188,730.35
  6 LoParts (2oz) w15: pad.2@114,727 116.83,727 273,727 ; 273,703 273,727 ; 282,694 350,694 357,687 357,585 ; R76.1@310,585.31 357,585 ; U10.3@334,777 329.43,777 285,777 273,765 273,727 ; R72.2@438.45,195 449,209 CR25.1@449.21,392.37 440.01,401.57 pad.8@400.44,401.57 373.93,401.57 341.5,434 341.5,511.5 357,527 357,585
NetC26_1: C26.1 C32.1 CR27.3 pad.8@262.5,558 | length 311.6
  6 LoParts (2oz) w12: CR27.3@249.37,604 254.68,604 CR27.3@262.5,596.18
  6 LoParts (2oz) w15: C32.1@251.74,302 C26.1@251.74,458 262.5,513 pad.8@262.5,558 CR27.3@262.5,596.18
NetC30_1: C30.1 pad.8@285,-125.31 R90.1 R91.2 U5.3 | length 252.2
  6 LoParts (2oz) w8: R90.1@185.68,-149.73 192.41,-143 241,-143 258.69,-125.31 pad.8@284.69,-125.31 ; U5.3@415,-97 382,-97 C30.1@369,-112.31 346.5,-112.5 331.5,-126 R91.2@322.27,-126.31 pad.8@285,-125.31 ; pad.8@284.69,-125.31 284.84,-125.16 pad.8@285,-125.31 ; pad.8@284.69,-125.31 pad.8@285,-125.31
NetCR3_1: CR3.1 CR4.1 pad.8@-75,-305 R6.1 | length 149
  6 LoParts (2oz) w8: CR4.1@-48.49,-220 CR3.1@-48.49,-270 -48.5,-293 -40,-302 R6.1@-39.67,-320
  6 LoParts (2oz) w10: pad.8@-75,-305 -75,-312 -67,-320 R6.1@-39.67,-320
NetCR4_2: CR4.2 pad.2@53,-260 pad.2@631,-317 pad.8@90,-190 Q5.1 R7.2 R97.2 | length 989.9
  2 RTNS (2oz) w15: pad.2@53,-260 53,-271.5 141.5,-360 336.5,-360 434,-262.5 576.5,-262.5 pad.2@631,-317
  6 LoParts (2oz) w8: CR4.2@8.51,-220 40.24,-220 Q5.1@52.61,-207.63
  6 LoParts (2oz) w10: R7.2@-5.3,-370 27.01,-370 52.61,-344.4 52.61,-260 Q5.1@52.61,-207.63 70.24,-190 pad.8@90,-190
  6 LoParts (2oz) w15: R97.2@631.32,-316.69 pad.2@631,-317 ; pad.2@631,-317 631.06,-316.42 pad.2@631,-317
NetCR5_2: CR5.2 pad.8@659.5,-396.5 Q7.1 R25.2 | length 230.2
  6 LoParts (2oz) w8: R25.2@584.69,-469 620,-469 CR5.2@620,-454.5
  6 LoParts (2oz) w12: CR5.2@620,-454.5 645.5,-430 645.5,-409 pad.8@659.5,-396.5
  6 LoParts (2oz) w15: pad.8@659.5,-396.5 660.4,-395.6 Q7.1@764.37,-395.6
NetCR6_1: CR6.1 pad.8@330,-275 Q5.3 Q6.1 Q8.1 R16.1 | length 937.1
  6 LoParts (2oz) w10: Q8.1@182.61,-200.63 199.74,-183.5 209,-183.5 230.5,-162 281,-162 283.5,-164.5 283.5,-258.5 300,-275 pad.8@330,-275 348,-293 348,-311.5 366.5,-330 376,-330 379,-333 379,-408.5 405,-434.5 440,-434.5 448.5,-426 ; CR6.1@482,-401 482,-370 464.5,-352.5 464.5,-309 516.56,-256.94 R16.1@516.56,-255
  6 LoParts (2oz) w12: Q5.3@90.01,-286.37 123.13,-286.37 182.61,-226.89 Q8.1@182.61,-200.63 ; Q6.1@427.4,-369.37 427.4,-379.9 448.5,-401 ; 448.5,-426 448.5,-401 ; CR6.1@493.5,-401 482,-401 448.5,-401
NetCR6_2: CR6.2 CR11.2 pad.2@567,-422 pad.2@568.01,-646 pad.8@565,-615 R98.1 U1.5 U1.6 U1.7 U1.8 | length 888.3
  1 TallParts (2oz) w10: U1.5@480.41,-619 U1.5@534.54,-619 ; U1.5@599,-619 599,-551 604.82,-545.18 U1.8@633.95,-545.18 ; U1.5@603.82,-595.18 U1.7@633.95,-595.18 ; U1.5@633.95,-695.18 609.18,-695.18 599,-685 599,-642 602.18,-645.18 633.94,-644.65 U1.6@633.95,-645.18
  1 TallParts (2oz) w20: U1.7@633.95,-595.18 650.82,-595.18 654.56,-591.44 R98.1@696,-591.44 696,-569 ; U1.8@633.95,-545.18 672.18,-545.18 680.99,-553.99 ; CR11.2@754.48,-494 754.48,-510.52 711.01,-553.99 ; 680.99,-553.99 711.01,-553.99 ; 680.99,-553.99 696,-569 ; 696,-569 711.01,-553.99
  5 Signal (2oz) w12: pad.2@567,-644.99 pad.2@568.01,-646
  5 Signal (2oz) w15: pad.2@567,-644.99 pad.2@567,-422
  6 LoParts (2oz) w10: pad.8@564.5,-615 pad.8@565,-615 568,-630.5 pad.2@568.01,-646
  6 LoParts (2oz) w12: CR6.2@547.74,-401.07 549.09,-402.41 550.55,-402.36 561,-402 567,-408 pad.2@567,-422
NetCR10_1: CR10.1 pad.8@185.01,-305 R64.2 | length 118.3
  6 LoParts (2oz) w10: R64.2@170.01,-374.69 187,-374 196,-362 196,-333 ; pad.8@185.01,-305 196,-317 196,-333 ; CR10.1@221.01,-333 196,-333
NetCR11_1: CR11.1 R17.2 R18.2 R19.2 | length 990.1
  1 TallParts (2oz) w35: R19.2@887,-228 940,-279 940,-493.52 CR11.1@939.52,-494 CR11.1@939.52,-495
  2 RTNS (2oz) w25: R17.2@397,-220 414.5,-225 R18.2@642.01,-225 642,-139.5 683,-100 856,-100 887,-131.5 R19.2@886.71,-226.46
NetCR12_1: CR12.1 CR14.1 CR29.1 pad.2@441,-594 pad.2@855.33,-424 pad.8@830,-395 R26.1 U1.1 U1.2 U1.3 | length 1292.8
  1 TallParts (2oz) w10: U1.3@378.05,-645.18 407.32,-645.18 415,-637.5 415,-552.5 407.68,-545.18 U1.1@378.05,-545.18 ; U1.2@378.05,-595.18 414.32,-595.18 ; 415.5,-595.5 439.5,-595.5 pad.2@441,-594
  1 TallParts (2oz) w12: U1.3@363,-646.5 364.32,-645.18 U1.3@378.05,-645.18
  1 TallParts (2oz) w15: CR12.1@10.01,-677.48 27.99,-659.5 333,-659.5 U1.3@363,-646.5
  2 RTNS (2oz) w15: pad.2@441,-594 447.5,-589.5 557.5,-589.5 720.55,-423.95 pad.2@855.33,-424
  6 LoParts (2oz) w10: CR29.1@395.63,-677.4 435,-637 435,-600 pad.2@441,-594 ; pad.8@830,-395 860.67,-395 ; pad.2@855.33,-424 R26.1@860.32,-420 860.67,-395 ; 861,-395 860.67,-395 ; CR14.1@875.63,-372.4 861,-372.4 860.67,-395
NetCR17_1: CR17.1 CR18.1 pad.2@18.01,-804 pad.2@133,-706 pad.2@438.5,-670 pad.8@-85,-893 R22.1 R63.1 U4.10 U7.5 | length 1000
  1 TallParts (2oz) w10: pad.2@18.01,-804 pad.2@133,-706
  1 TallParts (2oz) w12: U4.10@410.86,-813.41 443,-813 469,-787 469,-754.5 439,-724 pad.2@438.5,-670
  2 RTNS (2oz) w10: pad.2@133,-706 182,-657 425.5,-657 pad.2@438.5,-670
  6 LoParts (2oz) w6: pad.8@-85,-893 -85,-910 -73.5,-920 CR17.1@-48.49,-920
  6 LoParts (2oz) w10: CR17.1@-48.49,-920 -40,-918 6,-872 R22.1@6.55,-861.46 ; pad.2@438.5,-670 464.73,-695.73 R63.1@464.73,-723 R63.1@464.73,-723.32
  6 LoParts (2oz) w15: R22.1@6.55,-861.46 7,-838 18,-827 pad.2@18.01,-804 ; CR18.1@17.4,-803.39 CR18.1@17.4,-798.37 ; U7.5@132.5,-659.65 132.51,-705.51 pad.2@133,-706
NetCR17_2: CR17.2 pad.2@9.5,-911.5 pad.2@586.63,606.4 pad.8@54,-926.5 R8.2 U11.2 | length 2225.3
  5 Signal (2oz) w15: pad.2@9.5,-911.5 353,-911.5 397.01,-867.99 397,-763 392,-757 392,-734 404,-722 404,-692 397.01,-685.01 ; 397,-676 397,-685 ; pad.2@586.63,606.4 586.63,305.37 641,251 641,17 602,-16 570.5,-16 475,-111.5 475,-258 397,-336 397.01,-685.01
  6 LoParts (2oz) w15: CR17.2@8.51,-920 9.5,-920 CR17.2@21.5,-920 ; CR17.2@8.51,-912.49 pad.2@9.5,-911.5 CR17.2@9.5,-919.01 ; CR17.2@23,-921.5 28.5,-926.5 pad.8@54,-926.5 54.19,-926.69 R8.2@168,-926.69 ; pad.2@586.63,606.4 U11.2@600.63,606.4
NetCR18_2: CR18.2 CR18.3 CR22.1 pad.8@-69.99,-500 U7.7 | length 486
  6 LoParts (2oz) w10: CR22.1@-72.39,-549.63 -72.39,-697.59 -51.34,-719.63 ; CR18.2@-57.4,-798.37 -57.39,-746.39 -51.34,-740.34 -51.34,-719.63 ; CR18.3@-20,-719.96 CR18.3@-20,-719.63 ; U7.7@82.51,-669 82.51,-695.5 74.01,-704 28,-704 12.37,-719.63 CR18.3@-20,-719.63 ; -51.34,-719.63 CR18.3@-20,-719.63
  6 LoParts (2oz) w12: CR22.1@-72.39,-549.63 CR22.1@-67.4,-549.63 -69.99,-547.04 pad.8@-69.99,-500
NetCR19_1: CR19.1 pad.2@107.51,-481 pad.2@496,-482 pad.2@533,-127 pad.2@580,-794 pad.8@28,-662.5 R95.2 R96.2 U4.5 U7.3 | length 1632.7
  1 TallParts (2oz) w10: pad.2@580,-794 598,-812.5 U4.5@643.14,-812.64
  2 RTNS (2oz) w10: pad.2@107.51,-481 130.01,-502.5 476.5,-502.5 pad.2@496,-482
  5 Signal (2oz) w12: 496,-435.5 574,-357.5 574.5,-226 533.5,-185
  5 Signal (2oz) w15: 496,-435.5 pad.2@496,-482 488,-493 488,-548 536,-596 536,-756 pad.2@580,-794 ; pad.2@533,-127 533.5,-185
  6 LoParts (2oz) w6: 544.5,-123 R95.2@557.5,-107.5
  6 LoParts (2oz) w8: pad.2@533,-127 544.5,-123
  6 LoParts (2oz) w10: pad.8@28,-662.5 32,-657.5 32,-584 61,-555 94,-555 107.51,-541.49 U7.3@107.5,-490.35 pad.2@107.51,-481 108,-449 122,-435 CR19.1@122.42,-424.37 ; pad.2@496,-482 515,-482 519.5,-475 R96.2@518.69,-446.27 ; R95.2@557.5,-107.5 R95.2@565.31,-97.73
NetCR19_2: CR19.2 CR19.3 CR22.2 pad.8@27.5,-470 U7.1 | length 307
  6 LoParts (2oz) w10: CR22.2@7.4,-549.63 39,-550 57.5,-532 U7.1@57.5,-490.35 U7.1@57.51,-481 ; pad.8@27.5,-470 41.01,-481 U7.1@57.5,-481 ; U7.1@57.66,-490.35 U7.1@57.51,-481 ; CR19.3@87,-345.63 87,-367.5 47.61,-408.4 47.61,-424.37 47.61,-448.6 57.51,-458.5 U7.1@57.51,-481
NetCR20_2: CR20.2 pad.2@595,-860.5 pad.2@672,-519 pad.8@670,-540 R23.2 R30.1 R58.1 | length 993
  1 TallParts (2oz) w8: 500,-503.5 513,-496
  1 TallParts (2oz) w10: CR20.2@292.5,-582 350,-517 439.5,-517 455.5,-503.5 500,-503.5 ; 513,-496 528,-496 538,-504 650.01,-504 659,-504.5 pad.2@672,-519
  5 Signal (2oz) w10: pad.2@595,-860.5 624.01,-837 624,-564 pad.2@672,-519
  6 LoParts (2oz) w10: R58.1@577.44,-531 577.44,-532.44 581.44,-532.44 613,-564 630,-564 ; R58.1@577.73,-530.71 577.23,-530.21 577.26,-529.97 R58.1@578.01,-525 ; R23.2@630.86,-583.84 R23.2@629.7,-585 629.7,-564.3 630,-564 ; pad.2@672,-519 670,-521 pad.8@670,-540 670,-544 650,-564 630,-564
  6 LoParts (2oz) w12: pad.2@595,-860.5 605.57,-849.93 R30.1@605.57,-843
NetCR23_3: CR23.3 pad.8@939.61,272 Q9.1 R70.1 | length 365.4
  6 LoParts (2oz) w15: R70.1@687.78,284.94 687.6,303 703.24,317.63 CR23.3@796.61,317.63 822.98,317.63 868.61,272 pad.8@939.61,272 961.61,272 969.01,279.4 Q9.1@969.01,317.63
NetCR26_1: CR26.1 pad.8@15,210 R73.2 | length 249
  6 LoParts (2oz) w10: R73.2@-23.56,381 -4,381 3,373 3,291 9,285 9,220 pad.8@15,210
  6 LoParts (2oz) w15: CR26.1@-71.63,377.4 -24,377 R73.2@-23.56,381
NetCR26_2: CR26.2 pad.8@-162,301 R74.1 | length 146.1
  6 LoParts (2oz) w15: pad.8@-160,301 -84.5,301 CR26.2@-71.63,302.6 -23.58,302.5 -23.5,302.5 R74.1@-23.56,312
NetCR27_2: CR27.2 pad.8@175.01,675 R75.1 | length 210.9
  6 LoParts (2oz) w10: 69.44,614.56 90,594 ; 153,594 169.63,609.63
  6 LoParts (2oz) w12: 90,594 153,594
  6 LoParts (2oz) w15: 69.44,614.56 R75.1@69.44,643 ; 169.63,609.63 169.63,641.4 170.13,641.9 175.01,646.78 pad.8@175.01,675
NetCR28_1: CR28.1 E7.1 pad.2@313,-420 pad.2@978,-624 pad.8@281.01,-668 R24.2 | length 1483.3
  1 TallParts (2oz) w10: CR28.1@927,-624 939.52,-624 pad.2@978,-624
  2 RTNS (2oz) w10: 445,-752 471.5,-778 562.5,-778
  2 RTNS (2oz) w12: E7.1@300.01,-750 377,-750 407,-720 434.5,-720 444.5,-730 445,-752 ; 562.5,-778 576.5,-765 819,-765 960,-624 pad.2@978,-624
  5 Signal (2oz) w10: E7.1@300.01,-750 312.45,-737.56 pad.2@313,-420
  6 LoParts (2oz) w12: R24.2@297.44,-425 302.44,-420 pad.2@313,-420
  6 LoParts (2oz) w15: E7.1@240,-748.5 240,-708 259,-696 277.89,-689.13 281.01,-688 ; pad.8@281.01,-668 281.01,-688 ; E7.1@300.01,-750 281,-714 281.01,-688 ; E7.1@348.5,-747.5 350.5,-720.5 348.5,-703 347.76,-702.26 341.82,-697.53 337.01,-694.33 332,-691 305.97,-688.48 304.69,-688.35 300.01,-688 281.01,-688
NetCR28_2: CR28.2 pad.8@762,-606 R98.2 | length 96.9
  1 TallParts (2oz) w20: R98.2@696,-646.56 745.44,-646.56 754.48,-637.52 CR28.2@754.48,-623 754.48,-613.52 pad.8@762,-606
NetCR29_3: CR29.3 pad.2@375,-715 pad.2@495,-735 pad.2@839.5,-469.5 pad.8@930,-455 R21.2 R26.2 U1.4 | length 887.6
  1 TallParts (2oz) w12: pad.2@375,-715 375,-697.05 U1.4@378.05,-694
  2 RTNS (2oz) w15: pad.2@495,-735 518.5,-735 562.5,-691 594,-691 638.5,-646.5 677.5,-646.5 830.5,-493.5 pad.2@839.5,-469.5
  6 LoParts (2oz) w6: 445,-743 487,-743
  6 LoParts (2oz) w8: 426,-715 439,-727 440,-737 445,-743 ; 487,-743 pad.2@495,-735
  6 LoParts (2oz) w10: pad.2@375,-715 426,-715 ; pad.2@839.5,-469.5 854.5,-455.5 900,-455.5 ; R26.2@899.69,-420 900,-455.5 ; R21.2@905.69,-485 906,-481 906,-455.5 ; pad.8@930,-455 927.51,-455.5 906,-455.5 ; 900,-455.5 906,-455.5
  6 LoParts (2oz) w12: CR29.3@474.37,-640 474.5,-665.5 495,-687 pad.2@495,-735
NetE3_1: E3.1 pad.8@-154,140 U2.3 | length 641.1
  1 TallParts (2oz) w15: E3.1@-84.99,210 -138,210 -174,246 -174,458 -155,475 -59,475 -45.5,461.5 U2.3@-45,421
  6 LoParts (2oz) w6: pad.8@-154,146 -147,153 E3.1@-101.49,198.5
  6 LoParts (2oz) w15: E3.1@-150,199 -127.5,198.5 -101.49,198.5 -96.49,198.5 E3.1@-84.99,210
NetE4_1: E4.1 pad.8@15,820 U2.4 | length 429.9
  1 TallParts (2oz) w15: E4.1@-84.99,835 -85,568 U2.4@-45,527
  6 LoParts (2oz) w15: E4.1@-84.99,835 -2,835 pad.8@15,820
NetP1_5: P1.5 pad.2@324,-99 R84.1 | length 850.6
  2 RTNS (2oz) w15: P1.5@-124.99,-640 -75,-590.01 -75,-335 128,-132 267,-132 300,-99 pad.2@324,-99
  6 LoParts (2oz) w8: pad.2@324,-99 324,-85 R84.1@336.54,-78.55
NetP1_6: P1.6 pad.9 R22.2 | length 156.9
  6 LoParts (2oz) w8: pad.9@-95,-790 -83,-810 -81,-847 -67,-861
  6 LoParts (2oz) w10: P1.6@-124.99,-740 pad.9@-95,-790 ; -67,-861 R22.2@-48.57,-861.46
NetP2_3: P2.3 R47.2 R50.2 | length 404.6
  6 LoParts (2oz) w8: R50.2@740,-537 740,-525 749,-516 803.5,-516 819.5,-532 860.5,-532 884.5,-556 894,-556 ; R47.2@894,-573 894,-556 ; 997,-506 948,-556 894,-556
  6 LoParts (2oz) w10: 997,-506 997.01,-469 P2.3@1025,-440
NetP2_4: P2.4 pad.2@698.5,-526.5 pad.2@820,-570 pad.8@830.01,-665 R45.2 R48.2 | length 703.5
  2 RTNS (2oz) w12: pad.2@698.5,-526.5 778,-447.5 861,-447.5 881,-467.5 881,-540 ; pad.2@820,-570 850,-540 881,-540 ; P2.4@1025,-540 881,-540
  6 LoParts (2oz) w6: 830.01,-639 819,-628 819,-574 pad.2@820,-570 838,-570 R48.2@843,-575.31
  6 LoParts (2oz) w8: pad.8@830.01,-665 830.01,-639
  6 LoParts (2oz) w12: R45.2@695.01,-590.31 698.5,-586.83 pad.2@698.5,-526.5
NetP2_5: P2.5 R46.2 R49.2 | length 339.8
  6 LoParts (2oz) w6: 855.5,-550 869,-564 869,-588 874,-593 911.33,-593 923,-581 R46.2@945.01,-581.31
  6 LoParts (2oz) w8: R49.2@785,-537 789,-537 802.5,-550 855.5,-550 ; R46.2@945.01,-581.31 965,-569 992,-569 1025,-595 P2.5@1025,-640
NetP2_6: P2.6 R44.1 | length 379.9
  6 LoParts (2oz) w8: R44.1@800.01,-929.69 819.33,-929.69 827.01,-922 827.01,-793 847.01,-772 971.01,-772 1004.01,-740 P2.6@1025,-740 P2.6@1025.81,-740
NetP2_7: P2.7 pad.8@1055,-900 R43.1 | length 184.9
  6 LoParts (2oz) w10: R43.1@955.01,-929.69 R43.1@955.01,-930 1024.5,-930 pad.8@1055,-900 1055,-870.5 P2.7@1025,-840
NetQ6_2: pad.2@257.41,-201 pad.8@309.01,-312 pad.8@387.01,-455 Q6.2 Q8.2 R24.1 | length 310.1
  6 LoParts (2oz) w6: R24.1@352.56,-425 359,-436 pad.8@387.01,-455
  6 LoParts (2oz) w10: pad.2@257.41,-201 257.41,-261.41 pad.8@309.01,-312 309,-326 Q6.2@352.34,-369.15
  6 LoParts (2oz) w15: R24.1@352.56,-425 353,-393 Q6.2@352.68,-369.37
NetQ7_3: pad.8@802,-432.5 pad.8@940,-190 Q7.3 R20.1 R21.1 R97.1 | length 1489.6
  6 LoParts (2oz) w8: R20.1@677.92,87.73 678,48 673,43 673,-54 677.78,-59.78 677.78,-87.78 694.5,-104.5 764,-104.5 803.5,-136 886,-136 pad.8@940,-190 940,-288.5 914,-314.5 914,-361 920.48,-368.61 ; R21.1@864.86,-486.62 864.66,-486.46 870,-489.5 893.5,-514 936,-514 955,-495 955,-405 920.48,-368.61 ; 918,-366 920.48,-368.61 ; 921,-368.5 920.48,-368.61
  6 LoParts (2oz) w10: R97.1@685.12,-317 R97.1@685.56,-317 685,-289 707,-267 806.5,-267.5 823,-284 823,-356.5 804,-375.5 804,-430.5 pad.8@802,-432.5 815,-445 815,-475 831.07,-491 848.5,-491 853,-486.5 R21.1@864.66,-486.46
  6 LoParts (2oz) w15: Q7.3@685.63,-433 pad.8@801.87,-433
NetQ9_3: pad.8@879.61,414 Q9.3 R69.1 | length 447.7
  6 LoParts (2oz) w10: R69.1@593,283.94 593.6,320 617.3,344 617.6,344 630,356 776,356 787,358 809,358 819,356 858,356 879.61,377.77 pad.8@879.61,414 929,414 Q9.3@929.6,398.37
NetQ10_1: pad.8@315,10 Q10.1 R86.1 R87.1 R88.1 R89.1 | length 500.4
  6 LoParts (2oz) w8: R87.1@315,44.31 pad.8@315,10 304,-0.5 304,-41.5 314,-51.5 362.5,-51.5 374.5,-63.5 413,-64 422,-57 422,-4 441.5,16 442.5,16 479.37,16 R88.1@492.5,30.5
  6 LoParts (2oz) w10: R88.1@492.5,30.5 R88.1@499.6,33.31 508,29 519,17.5 R86.1@519.68,-15.73 548,-16 558,-26 R89.1@591.32,-26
